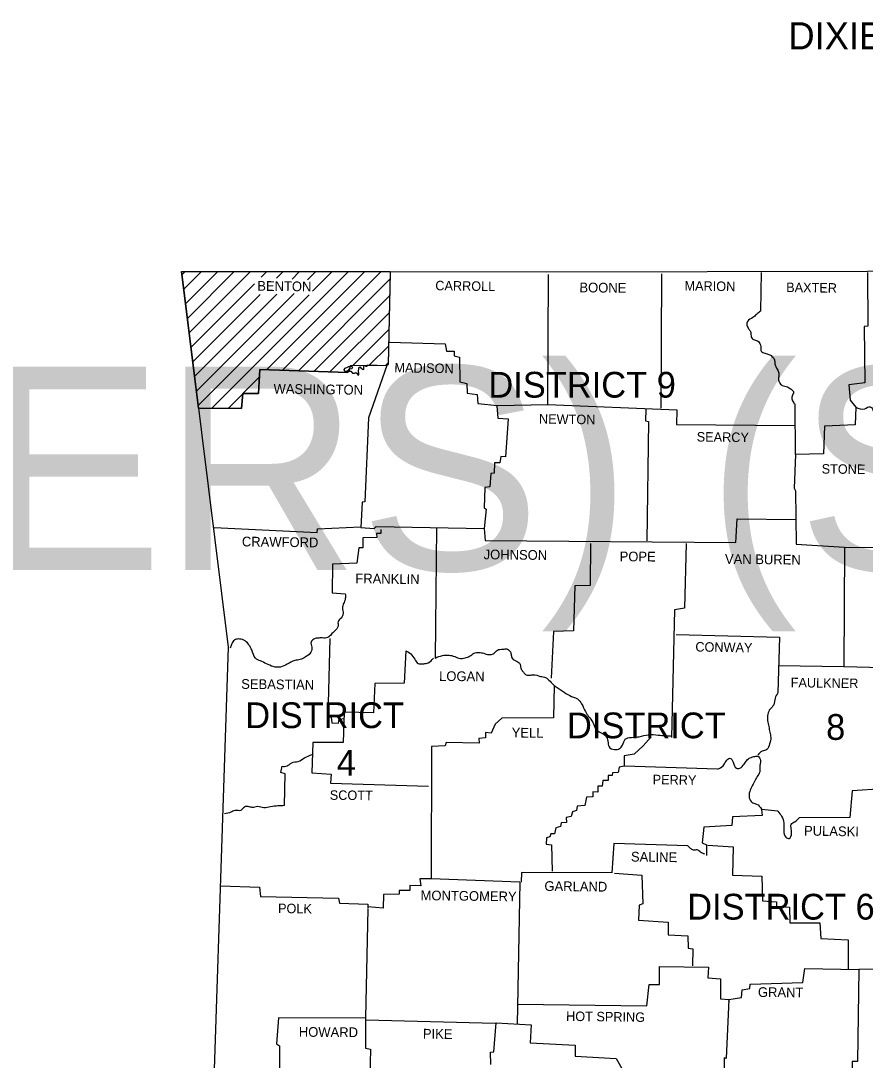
# Model space of a CAD drawing. Extents: x 309389.3 to 309420.2, y 336441.4 to 336461.2.
# Drawn here: x 309413.135 to 309416.789, y 336456.398 to 336460.893 of the extents above; entities that cross this region are included whole.
import ezdxf

# ---------------------------------------------------------------- set-up
doc = ezdxf.new("R2010")
doc.units = 0
doc.layers.add('Level 1', color=7, linetype='Continuous')
doc.layers.add('Level 63', color=7, linetype='Continuous')

msp = doc.modelspace()

# ---------------------------------------------------------------- linework, layer by layer
at = {"layer": 'Level 63'}
for p, q in [((309413.8323, 336459.795), (309413.8464, 336459.8092)), ((309413.8401, 336459.7321), (309413.9171, 336459.8092)), ((309413.8479, 336459.6693), (309413.9878, 336459.8091)), ((309413.8557, 336459.6064), (309414.0584, 336459.8091)), ((309413.8636, 336459.5435), (309414.1291, 336459.809)), ((309413.9618, 336459.2175), (309414.5531, 336459.8088)), ((309414.1751, 336459.7843), (309414.1998, 336459.809)), ((309414.1999, 336459.3848), (309414.6238, 336459.8087)), ((309414.2417, 336459.7802), (309414.2704, 336459.8089)), ((309414.2681, 336459.3824), (309414.6944, 336459.8087)), ((309414.3087, 336459.7765), (309414.3411, 336459.8089)), ((309414.3762, 336459.7733), (309414.4118, 336459.8089)), ((309414.3976, 336459.724), (309414.4824, 336459.8088)), ((309414.3364, 336459.3799), (309414.7322, 336459.7757)), ((309413.8714, 336459.4806), (309414.1467, 336459.7559)), ((309413.8949, 336459.292), (309414.3176, 336459.7147)), ((309413.8792, 336459.4178), (309414.1705, 336459.709)), ((309413.8871, 336459.3549), (309414.2428, 336459.7106)), ((309413.9027, 336459.2291), (309414.3823, 336459.7087)), ((309414.4046, 336459.3775), (309414.7306, 336459.7034)), ((309414.4729, 336459.375), (309414.729, 336459.6311)), ((309414.5702, 336459.4016), (309414.7274, 336459.5588)), ((309414.6414, 336459.4021), (309414.7258, 336459.4864)), ((309414.7125, 336459.4025), (309414.7241, 336459.4141)), ((309414.5412, 336459.3726), (309414.5561, 336459.3875)), ((309414.0964, 336459.2813), (309414.1668, 336459.3518)), ((309414.0322, 336459.2171), (309414.0953, 336459.2803)), ((309415.2939, 336457.1688), (309415.2826, 336456.5548))]:
    msp.add_line(p, q, dxfattribs=at)
for points in [[(309413.8305, 336459.8092), (309415.4112, 336459.8082), (309416.7984, 336459.8112), (309418.4349, 336459.8366), (309419.1935, 336459.8542)], [(309413.8305, 336459.8092), (309414.0328, 336458.1845), (309413.9449, 336455.5323)], [(309414.7328, 336459.8034), (309414.724, 336459.4074)], [(309416.338, 336459.8053), (309416.336, 336459.6381)], [(309416.7984, 336459.8053), (309416.8004, 336459.5726), (309416.7838, 336459.5717), (309416.7867, 336459.3282), (309416.7183, 336459.3185), (309416.7241, 336459.253), (309416.7476, 336459.2227), (309416.7457, 336459.1454), (309416.6127, 336459.1406), (309416.6078, 336459.0213), (309416.4866, 336459.0174), (309416.4807, 336458.8727), (309416.4876, 336458.861), (309416.4905, 336458.6302), (309416.6997, 336458.6166), (309416.6968, 336458.1014), (309416.863, 336458.0965), (309416.863, 336457.5725), (309416.732, 336457.5627), (309416.7222, 336457.4474), (309416.5022, 336457.4464)], [(309414.7308, 336459.5042), (309414.9713, 336459.4964), (309414.9772, 336459.4651), (309415.0104, 336459.4641), (309415.0095, 336459.4446), (309415.0329, 336459.4387), (309415.0349, 336459.3322), (309415.0652, 336459.3253), (309415.0671, 336459.2833), (309415.1101, 336459.2774), (309415.1121, 336459.2383), (309415.1972, 336459.2295), (309415.4161, 336459.2344), (309415.4181, 336459.7965)], [(309415.9079, 336459.7985), (309415.9049, 336459.2178)], [(309413.9077, 336459.2178), (309414.0905, 336459.2168), (309414.0954, 336459.2813), (309414.1629, 336459.2813), (309414.1687, 336459.3859), (309414.55, 336459.3722), (309414.5519, 336459.3769), (309414.5458, 336459.3782), (309414.5365, 336459.3761), (309414.5346, 336459.3853), (309414.5389, 336459.3912), (309414.5617, 336459.4016), (309414.5675, 336459.3986), (309414.57, 336459.3922), (309414.5657, 336459.3884), (309414.5562, 336459.3873), (309414.5554, 336459.3775), (309414.5631, 336459.3787), (309414.5705, 336459.3691), (309414.5796, 336459.3688), (309414.5852, 336459.3718), (309414.5907, 336459.3676), (309414.595, 336459.3602), (309414.5983, 336459.3629), (309414.5982, 336459.3699), (309414.5958, 336459.3743), (309414.5972, 336459.3929), (309414.6029, 336459.3965), (309414.6069, 336459.3921), (309414.6136, 336459.3865), (309414.6189, 336459.3854), (309414.6187, 336459.4008), (309414.6226, 336459.4027), (309414.6274, 336459.4001), (309414.6332, 336459.4003), (309414.6356, 336459.4062), (309414.7191, 336459.4025), (309414.6399, 336459.1757), (309414.6243, 336458.8131), (309414.6126, 336458.8121), (309414.6067, 336458.7026), (309414.6644, 336458.6977), (309414.6732, 336458.7065), (309415.1395, 336458.6977), (309415.1444, 336458.6459)], [(309415.1952, 336459.2276), (309415.1991, 336459.1748), (309415.2441, 336459.1718), (309415.2323, 336459.0076), (309415.2118, 336459.0086), (309415.2079, 336458.9822), (309415.1844, 336458.9822), (309415.1835, 336458.9372), (309415.1688, 336458.9362), (309415.1639, 336458.8786), (309415.1424, 336458.8756), (309415.1395, 336458.7876), (309415.1493, 336458.7808), (309415.1395, 336458.6977)], [(309415.4161, 336459.2344), (309415.9734, 336459.2109), (309415.9724, 336459.1474), (309416.4837, 336459.1435)], [(309416.4866, 336459.0174), (309416.4856, 336459.2373)], [(309415.8394, 336459.2139), (309415.8385, 336459.163), (309415.8512, 336459.1601), (309415.8433, 336458.6439)], [(309415.1444, 336458.6459), (309416.2295, 336458.6371), (309416.2344, 336458.7397), (309416.4866, 336458.7368)], [(309413.9722, 336458.7016), (309414.417, 336458.6811), (309414.419, 336458.6967), (309414.6047, 336458.7055)], [(309414.6927, 336458.6938), (309414.6927, 336458.6762), (309414.6741, 336458.6762), (309414.6751, 336458.6586), (309414.6155, 336458.6576), (309414.6145, 336458.6136), (309414.5979, 336458.6136), (309414.5891, 336458.5481), (309414.4835, 336458.5432), (309414.4825, 336458.4191), (309414.5392, 336458.4152)], [(309414.9342, 336458.7016), (309414.9273, 336458.1375)], [(309415.6002, 336458.6335), (309415.5992, 336458.4507), (309415.5318, 336458.4497), (309415.5259, 336458.2552), (309415.4399, 336458.2522), (309415.4301, 336458.0509)], [(309416.6997, 336458.6166), (309417.2022, 336458.6136), (309417.2452, 336458.6342), (309417.2423, 336458.2519), (309417.2129, 336458.2392), (309417.1865, 336458.2167), (309417.1778, 336458.2079), (309417.1768, 336458.0984), (309416.8571, 336458.0984)], [(309416.0142, 336458.6325), (309416.0071, 336458.3529), (309415.9641, 336458.3457), (309415.9498, 336457.7938)], [(309415.9704, 336458.2392), (309416.4172, 336458.2285), (309416.4113, 336457.987)], [(309414.4728, 336458.2216), (309414.463, 336457.8853), (309414.4776, 336457.8814), (309414.4806, 336457.858), (309414.5099, 336457.856), (309414.5128, 336457.8726), (309414.5363, 336457.8765)], [(309414.8012, 336458.1688), (309414.7944, 336458.029), (309414.6673, 336458.0281), (309414.6605, 336457.901), (309414.5343, 336457.9039), (309414.5304, 336457.7729), (309414.3985, 336457.7719), (309414.3946, 336457.6409), (309414.4776, 336457.636), (309414.4747, 336457.596), (309414.899, 336457.5842)], [(309416.4123, 336458.1053), (309416.6968, 336458.1014)], [(309415.4435, 336458.0193), (309415.4396, 336457.8785), (309415.2167, 336457.8775), (309415.1874, 336457.8521), (309415.1708, 336457.813), (309415.1463, 336457.8149), (309415.1453, 336457.7925), (309415.117, 336457.7895), (309415.118, 336457.769), (309414.9762, 336457.7729), (309414.9713, 336457.7573), (309414.9127, 336457.7553), (309414.9107, 336457.1848)], [(309415.8629, 336457.7964), (309415.8277, 336457.7582), (309415.7896, 336457.7221), (309415.7456, 336457.7152), (309415.7456, 336457.6693), (309415.7241, 336457.6663), (309415.7202, 336457.6429), (309415.6957, 336457.6409), (309415.6938, 336457.6302), (309415.6772, 336457.6292), (309415.6762, 336457.6087), (309415.6527, 336457.6077), (309415.6508, 336457.5842), (309415.6312, 336457.5842), (309415.6322, 336457.5569), (309415.6107, 336457.5588), (309415.6097, 336457.5373), (309415.5833, 336457.5353), (309415.5755, 336457.5002), (309415.5422, 336457.4972), (309415.5393, 336457.4777), (309415.5217, 336457.4728), (309415.5168, 336457.4523), (309415.4943, 336457.4474), (309415.4963, 336457.4268), (309415.4738, 336457.4249), (309415.4699, 336457.4092), (309415.4494, 336457.4034), (309415.4445, 336457.377), (309415.4288, 336457.378), (309415.424, 336457.3643), (309415.4093, 336457.3594), (309415.4083, 336457.333), (309415.4308, 336457.3291), (309415.4347, 336457.2157)], [(309414.2763, 336457.4992), (309414.2792, 336457.637), (309414.2596, 336457.6429), (309414.2655, 336457.6693)], [(309416.1493, 336457.6575), (309415.7466, 336457.6703)], [(309416.4103, 336457.4747), (309416.34, 336457.4826), (309416.3429, 336457.4562), (309416.2148, 336457.4513), (309416.2109, 336457.4132), (309416.0907, 336457.4063), (309416.0838, 336457.3379), (309416.1014, 336457.3291), (309416.1014, 336457.2841)], [(309416.0213, 336457.3252), (309415.7016, 336457.3349), (309415.6928, 336457.2088), (309415.3018, 336457.2108), (309415.3002, 336457.1685)], [(309416.1083, 336457.3281), (309416.2178, 336457.3213), (309416.2138, 336457.1991), (309416.3419, 336457.1942), (309416.3439, 336457.0876), (309416.4045, 336457.0827), (309416.4045, 336457.0642), (309416.4612, 336457.0602), (309416.4631, 336456.9918), (309416.5922, 336456.9918), (309416.5961, 336456.9244), (309416.7154, 336456.9185), (309416.7144, 336456.7914)], [(309415.7045, 336457.2069), (309415.8228, 336457.1981), (309415.8267, 336457.0749), (309415.8101, 336457.069), (309415.8081, 336457.0035), (309415.9362, 336456.9947), (309415.9362, 336456.941), (309416.0213, 336456.9361), (309416.0222, 336456.8823), (309416.0428, 336456.8794), (309416.0418, 336456.807)], [(309413.9986, 336457.1531), (309414.1678, 336457.1472), (309414.1717, 336457.1062), (309414.5099, 336457.0993), (309414.5138, 336457.0778), (309414.637, 336457.0739), (309414.636, 336457.0554)], [(309414.9107, 336457.1848), (309414.9107, 336457.1834), (309414.8618, 336457.1824), (309414.8658, 336457.1531), (309414.8188, 336457.1541), (309414.8178, 336457.1326), (309414.7719, 336457.1326), (309414.7729, 336457.1169), (309414.7044, 336457.115), (309414.7035, 336457.0554), (309414.6371, 336457.0612)], [(309415.2939, 336457.1688), (309414.9107, 336457.1834)], [(309414.6368, 336457.0536), (309414.6263, 336456.5822)], [(309417.8806, 336456.9038), (309417.5111, 336456.9136), (309417.5092, 336456.7934), (309416.7613, 336456.7904)], [(309415.2842, 336456.6409), (309415.8433, 336456.633), (309415.8541, 336456.7259), (309415.8981, 336456.7259), (309415.8991, 336456.8041), (309416.1102, 336456.8012), (309416.1083, 336456.7543), (309416.163, 336456.7503), (309416.163, 336456.6643), (309416.1982, 336456.6614), (309416.1978, 336456.6524)], [(309416.1982, 336456.6614), (309416.253, 336456.6692), (309416.2569, 336456.7024), (309416.2891, 336456.7083), (309416.2911, 336456.7279), (309416.5189, 336456.7347), (309416.5277, 336456.7943), (309416.7613, 336456.7904)], [(309416.7613, 336456.7904), (309416.7554, 336456.3935), (309416.7329, 336456.3925), (309416.73, 336456.1472)], [(309416.1982, 336456.6614), (309416.1865, 336456.4053), (309416.1777, 336456.4082), (309416.1787, 336456.2752)], [(309414.6253, 336456.5802), (309414.2499, 336456.5812), (309414.2411, 336456.4698), (309414.2548, 336456.46), (309414.2538, 336456.3349), (309413.9869, 336456.3466)], [(309414.6262, 336456.5802), (309414.6262, 336456.4502), (309414.6477, 336456.4463), (309414.6458, 336456.3251), (309414.7748, 336456.3153), (309414.7592, 336455.6691), (309414.4933, 336455.676)], [(309414.6282, 336456.5734), (309415.1874, 336456.5587)], [(309415.1688, 336456.3798), (309415.1668, 336456.4336), (309415.1825, 336456.4346), (309415.1923, 336456.5607), (309415.3428, 336456.5509), (309415.3389, 336456.4737), (309415.5334, 336456.4629), (309415.5344, 336456.416), (309415.7104, 336456.4053), (309415.7407, 336456.3525), (309415.7221, 336456.329), (309415.7309, 336456.2928), (309416.3683, 336456.2694)]]:
    msp.add_lwpolyline(points, dxfattribs=at)
msp.add_lwpolyline([(309413.8305, 336459.8092), (309414.7329, 336459.8087), (309414.724, 336459.4074), (309414.7191, 336459.4025), (309414.5617, 336459.4016), (309414.55, 336459.3722), (309414.1687, 336459.3859), (309414.1629, 336459.2813), (309414.0954, 336459.2813), (309414.0905, 336459.2168), (309413.9041, 336459.2178)], close=True, dxfattribs=at)
for points in [[(309416.336, 336459.6381), (309416.3184, 336459.6235), (309416.3028, 336459.6098), (309416.2793, 336459.5932), (309416.2764, 336459.5775), (309416.2842, 336459.5619), (309416.2921, 336459.5492), (309416.295, 336459.5316), (309416.3018, 336459.5169), (309416.3184, 336459.5111), (309416.3321, 336459.4983), (309416.337, 336459.4808), (309416.339, 336459.4641), (309416.3546, 336459.4563), (309416.3722, 336459.4504), (309416.3888, 336459.4387), (309416.3967, 336459.4241), (309416.3986, 336459.4055), (309416.4055, 336459.3908), (309416.4133, 336459.3732), (309416.4152, 336459.3586), (309416.4133, 336459.3439), (309416.4172, 336459.3302), (309416.4299, 336459.3165), (309416.4524, 336459.3097), (309416.468, 336459.2999), (309416.4788, 336459.2862), (309416.4719, 336459.2696), (309416.4729, 336459.2549), (309416.4817, 336459.2373)], [(309416.7476, 336459.2227), (309416.7867, 336459.2158), (309416.8102, 336459.2246), (309416.8268, 336459.1992), (309416.8356, 336459.1797), (309416.8503, 336459.1513), (309416.8737, 336459.1425), (309416.8913, 336459.1269), (309416.8913, 336459.1102), (309416.8757, 336459.0946), (309416.8639, 336459.079), (309416.8679, 336459.0604), (309416.8718, 336459.035), (309416.8718, 336459.0105), (309416.8659, 336458.988), (309416.861, 336458.9675), (309416.8659, 336458.9499), (309416.8845, 336458.9529), (309416.904, 336458.9675), (309416.9246, 336458.9675), (309416.9441, 336458.9568), (309416.9646, 336458.9382), (309416.9852, 336458.9421), (309417.0018, 336458.947), (309417.0252, 336458.9538), (309417.0419, 336458.945), (309417.0565, 336458.9333), (309417.0741, 336458.9147), (309417.0907, 336458.903), (309417.1123, 336458.8922), (309417.1386, 336458.8854), (309417.1631, 336458.8688), (309417.167, 336458.8404), (309417.166, 336458.816), (309417.1641, 336458.7857), (309417.1621, 336458.7524), (309417.165, 336458.7202), (309417.1758, 336458.6987), (309417.1895, 336458.6733), (309417.1934, 336458.6498), (309417.1924, 336458.6127)], [(309414.5392, 336458.4152), (309414.5392, 336458.3946), (309414.5314, 336458.3731), (309414.5265, 336458.3546), (309414.5295, 336458.3301), (309414.5207, 336458.3106), (309414.508, 336458.2949), (309414.508, 336458.2754), (309414.4933, 336458.2549), (309414.4776, 336458.2392), (309414.464, 336458.2265), (309414.4395, 336458.2245), (309414.419, 336458.2236), (309414.3985, 336458.2167), (309414.3906, 336458.2021), (309414.3946, 336458.1796), (309414.3867, 336458.1581), (309414.3662, 336458.1415), (309414.3437, 336458.1307), (309414.3203, 336458.1268), (309414.288, 336458.1111), (309414.2587, 336458.0984), (309414.2274, 336458.1004), (309414.1981, 336458.1131), (309414.1717, 336458.1248), (309414.1511, 336458.1366), (309414.1345, 336458.1727), (309414.1238, 336458.1923), (309414.1052, 336458.2118), (309414.0827, 336458.2197), (309414.0641, 336458.2177), (309414.0416, 336458.1796)], [(309414.8012, 336458.1688), (309414.8227, 336458.1551), (309414.8394, 336458.1327), (309414.854, 336458.1141), (309414.8785, 336458.1131), (309414.898, 336458.117), (309414.9205, 336458.1366)], [(309414.9273, 336458.1375), (309414.9596, 336458.1483), (309414.9831, 336458.1503), (309415.0065, 336458.1463), (309415.031, 336458.1366), (309415.0574, 336458.1385), (309415.0769, 336458.1454), (309415.0965, 336458.1581), (309415.118, 336458.162), (309415.1385, 336458.1581), (309415.16, 336458.1522), (309415.1835, 336458.1591), (309415.1972, 336458.1718), (309415.2206, 336458.1757), (309415.2411, 336458.1757), (309415.2558, 336458.1591), (309415.2587, 336458.1415), (309415.2773, 336458.1248), (309415.2939, 336458.1141), (309415.2988, 336458.0936), (309415.3076, 336458.0789), (309415.3164, 336458.0691), (309415.3291, 336458.0632), (309415.3506, 336458.0652), (309415.3839, 336458.0584), (309415.4054, 336458.0535), (309415.4249, 336458.0369), (309415.4435, 336458.0193)], [(309415.4435, 336458.0193), (309415.4777, 336457.9958), (309415.51, 336457.9753), (309415.5432, 336457.9606), (309415.5618, 336457.9391), (309415.5784, 336457.9059), (309415.5921, 336457.8853), (309415.6097, 336457.8599), (309415.6224, 336457.8316), (309415.6429, 336457.8159), (309415.6644, 336457.8022), (309415.6752, 336457.7778), (309415.6801, 336457.7534), (309415.7035, 336457.7416), (309415.726, 336457.7465), (309415.7387, 336457.7612), (309415.7505, 336457.7866), (309415.7769, 336457.7944), (309415.8111, 336457.7973), (309415.8502, 336457.8061), (309415.8932, 336457.8042), (309415.9538, 336457.8003)], [(309416.4113, 336457.987), (309416.3986, 336457.9645), (309416.3927, 336457.9352), (309416.3771, 336457.9166), (309416.3673, 336457.8951), (309416.3664, 336457.8668), (309416.3712, 336457.8413), (309416.3761, 336457.8169), (309416.38, 336457.7944), (309416.3751, 336457.7661), (309416.3624, 336457.7416), (309416.3429, 336457.7348), (309416.3243, 336457.7182)], [(309414.2655, 336457.6693), (309414.287, 336457.6712), (309414.3075, 336457.6849), (309414.3349, 336457.6908), (309414.3623, 336457.7054), (309414.3965, 336457.7211)], [(309416.1493, 336457.6575), (309416.1738, 336457.6712), (309416.1865, 336457.6918), (309416.2021, 336457.7045), (309416.2178, 336457.6869), (309416.2314, 336457.6615), (309416.2461, 336457.6615), (309416.2647, 336457.6791), (309416.2764, 336457.6947), (309416.2911, 336457.7064), (309416.3067, 336457.7113), (309416.3233, 336457.7133), (309416.336, 336457.6947), (309416.3321, 336457.6654), (309416.3321, 336457.6458), (309416.3214, 336457.6253), (309416.3097, 336457.6038), (309416.2969, 336457.5793), (309416.2872, 336457.5529), (309416.2891, 336457.5275), (309416.3028, 336457.5109), (309416.3184, 336457.506), (309416.34, 336457.4845)], [(309414.2763, 336457.4992), (309414.2479, 336457.4982), (309414.2157, 336457.4943), (309414.1863, 336457.4904), (309414.1599, 336457.4953), (309414.1355, 336457.4914), (309414.1189, 336457.4953), (309414.0983, 336457.4904), (309414.0866, 336457.4786), (309414.0622, 336457.4786), (309414.0446, 336457.4708), (309414.0162, 336457.464)], [(309416.4103, 336457.4747), (309416.427, 336457.4532), (309416.4367, 336457.4239), (309416.4367, 336457.3907), (309416.4446, 336457.3633), (309416.4602, 336457.3574), (309416.47, 336457.3809), (309416.468, 336457.4044), (309416.468, 336457.418), (309416.4846, 336457.4298), (309416.5022, 336457.4464)], [(309416.0946, 336457.289), (309416.076, 336457.2988), (309416.0613, 336457.3076), (309416.0457, 336457.3066), (309416.033, 336457.3144), (309416.0213, 336457.3252)]]:
    msp.add_spline(points, degree=3, dxfattribs=at)

# ---------------------------------------------------------------- texts
at = {"layer": 'Level 1'}
for s, height, p in [('DIXIELAND RD. - 8TH ST. (ROGERS) (S)', 0.117311, (309416.4565, 336460.7698)), ('DIXIELAND RD. - 8TH ST.  (ROGERS) (S)', 0.879831, (309395.2502, 336458.5178))]:
    msp.add_text(s, height=height, dxfattribs=at).set_placement(p)
at = {"layer": 'Level 63'}
for s, height, rotation, p in [('BENTON', 0.04204, 359.2527, (309414.158, 336459.7261)), ('CARROLL', 0.04106, 359.1481, (309414.9283, 336459.7281)), ('BOONE', 0.04204, 359.4001, (309415.552, 336459.7193)), ('MARION', 0.04106, 359.1854, (309416.0066, 336459.7271)), ('BAXTER', 0.04106, 359.2559, (309416.4465, 336459.7203)), ('MADISON', 0.04106, 359.0906, (309414.7514, 336459.3732)), ('WASHINGTON', 0.04203, 359.232, (309414.2284, 336459.2813)), ('NEWTON', 0.04106, 359.2717, (309415.377, 336459.1513)), ('SEARCY', 0.04105, 359.2527, (309416.0594, 336459.0741)), ('STONE', 0.04105, 359.4001, (309416.6, 336458.9353)), ('CRAWFORD', 0.04203, 359.2771, (309414.0915, 336458.6205)), ('JOHNSON', 0.04204, 359.3514, (309415.1375, 336458.5648)), ('POPE', 0.04204, 359.6155, (309415.726, 336458.556)), ('VAN BUREN', 0.04204, 359.3508, (309416.1816, 336458.5452)), ('FRANKLIN', 0.04204, 359.1815, (309414.5823, 336458.4611)), ('CONWAY', 0.04105, 359.0371, (309416.0535, 336458.1659)), ('LOGAN', 0.04204, 359.3969, (309414.9449, 336458.0388)), ('FAULKNER', 0.04106, 359.2486, (309416.4661, 336458.0114)), ('SEBASTIAN', 0.04203, 359.2816, (309414.0886, 336458.0046)), ('YELL', 0.04204, 359.1987, (309415.2587, 336457.7944)), ('PERRY', 0.04106, 359.0858, (309415.8688, 336457.592)), ('SCOTT', 0.04106, 359.4063, (309414.4718, 336457.5246)), ('PULASKI', 0.04204, 359.053, (309416.5237, 336457.3701)), ('SALINE', 0.04204, 359.1491, (309415.7749, 336457.2577)), ('GARLAND', 0.04204, 359.3658, (309415.4005, 336457.1306)), ('MONTGOMERY', 0.04204, 359.2944, (309414.8648, 336457.0905)), ('POLK', 0.04105, 359.2152, (309414.2479, 336457.0348)), ('GRANT', 0.04204, 359.4032, (309416.3243, 336456.6721)), ('HOT SPRING', 0.04106, 359.2216, (309415.4943, 336456.5685)), ('HOWARD', 0.04204, 359.5145, (309414.3379, 336456.5001)), ('PIKE', 0.04203, 359.0452, (309414.8745, 336456.4923))]:
    msp.add_text(s, height=height, rotation=rotation, dxfattribs=at).set_placement(p)
for s, height, p in [('DISTRICT 9', 0.11144, (309415.1581, 336459.2637)), ('DISTRICT', 0.11144, (309414.1062, 336457.8345)), ('DISTRICT', 0.11144, (309415.4983, 336457.7905)), ('8', 0.1114, (309416.6195, 336457.7837)), ('4', 0.1114, (309414.5021, 336457.6292)), ('DISTRICT 6', 0.11144, (309416.0183, 336457.0065))]:
    msp.add_text(s, height=height, dxfattribs=at).set_placement(p)

doc.saveas('drawing.dxf')
